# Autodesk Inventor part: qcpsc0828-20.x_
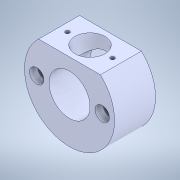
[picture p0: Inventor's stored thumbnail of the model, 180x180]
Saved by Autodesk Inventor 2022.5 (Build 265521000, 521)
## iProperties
Created: 2023-04
Part Number: qcpsc0828-20.x_
Material: Generic
Document SubType Name: Modeling
Designer: ImaoCorp
Density: 1 g/cm^3
Appearance: Default
Sending System: SOLIDWORKS 2021-2021301
MC: AMD64
MC_MODEL: Intel64 Family 6 Model 60 Stepping 3, GenuineIntel
OS: Windows_NT
FRU: Parasolid Version 32.1, build 255,  1- 1-2021
FORMAT: text
GUISE: transmit
KEY: qcpsc0828-20
FILE: qcpsc0828-20.x_t
DATE: Fri Apr  7 10:54:05 2023
Author: ImaoCorp
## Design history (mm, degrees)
feature "Base1"
node "ソリッド1"
